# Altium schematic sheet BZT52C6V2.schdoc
size 127 x 101 mm
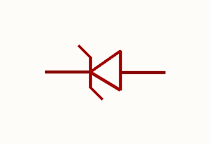
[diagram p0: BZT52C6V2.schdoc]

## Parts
D?  bzt52c6v2_c173405  [SOD-123_L2.8-W1.8-LS3.7-RD]  (value not drawn)

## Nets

Not connected (* = marked no-connect by the designer): D? 1 2

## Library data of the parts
D? = bzt52c6v2_c173405: 二极管配置:1个独立式;稳压值(标称值):6.2V;稳压值(范围):5.89V~6.51V;耗散功率(Pd):500mW;; Manufacturer: MDD(辰达半导体); AddInBom: yes; ModelId: 7884390a25fb4c08947731ebfba7e3f8; ModelTransform: 144.8816,62.992,0,0,0,0,0,0,0; Diode Configuration: 1个独立式; Zener Voltage(Nom): 6.2V; Reverse Leakage Current (Ir): 1uA@3V; Pd - Power Dissipation: 500mW; Impedance(Zzt): 50Ω; Tolerance: ±5%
